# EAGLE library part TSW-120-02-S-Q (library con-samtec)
THROUGH-HOLE .025" SQ POST HEADER Source: Samtec TSW.pdf
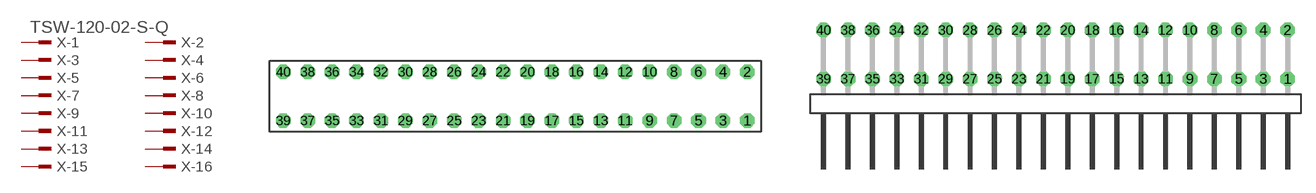
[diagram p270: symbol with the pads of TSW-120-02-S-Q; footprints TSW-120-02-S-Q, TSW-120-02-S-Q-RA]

Designator prefix X; gates -1=MPINV -2=MPIN -3=MPIN -4=MPIN -5=MPIN -6=MPIN -7=MPIN -8=MPIN -9=MPIN -10=MPIN -11=MPIN -12=MPIN -13=MPIN -14=MPIN -15=MPIN -16=MPIN -17=MPIN -18=MPIN -19=MPIN -20=MPIN -21=MPIN -22=MPIN -23=MPIN -24=MPIN -25=MPIN -26=MPIN -27=MPIN -28=MPIN -29=MPIN -30=MPIN -31=MPIN -32=MPIN -33=MPIN -34=MPIN -35=MPIN -36=MPIN -37=MPIN -38=MPIN -39=MPIN -40=MPIN

## TSW-120-02-S-Q (OC_FARNELL: unknown; OC_NEWARK: unknown)  [TSW-120-02-S-Q]
1  -1:1  pas
2  -2:1  pas
3  -3:1  pas
4  -4:1  pas
5  -5:1  pas
6  -6:1  pas
7  -7:1  pas
8  -8:1  pas
9  -9:1  pas
10  -10:1  pas
11  -11:1  pas
12  -12:1  pas
13  -13:1  pas
14  -14:1  pas
15  -15:1  pas
16  -16:1  pas
17  -17:1  pas
18  -18:1  pas
19  -19:1  pas
20  -20:1  pas
21  -21:1  pas
22  -22:1  pas
23  -23:1  pas
24  -24:1  pas
25  -25:1  pas
26  -26:1  pas
27  -27:1  pas
28  -28:1  pas
29  -29:1  pas
30  -30:1  pas
31  -31:1  pas
32  -32:1  pas
33  -33:1  pas
34  -34:1  pas
35  -35:1  pas
36  -36:1  pas
37  -37:1  pas
38  -38:1  pas
39  -39:1  pas
40  -40:1  pas

## TSW-120-02-S-Q-RA (OC_FARNELL: unknown; OC_NEWARK: unknown)  [TSW-120-02-S-Q-RA]
Pads as for TSW-120-02-S-Q

## Footprint TSW-120-02-S-Q (pad centres in mm)
THROUGH-HOLE .025" SQ POST HEADER Source: Samtec TSW.pdf
drill 1 pad 1.5 octagon: 1 24.13,-2.54; 2 24.13,2.54; 3 21.59,-2.54; 4 21.59,2.54; 5 19.05,-2.54; 6 19.05,2.54; 7 16.51,-2.54; 8 16.51,2.54; 9 13.97,-2.54; 10 13.97,2.54; 11 11.43,-2.54; 12 11.43,2.54; 13 8.89,-2.54; 14 8.89,2.54; 15 6.35,-2.54; 16 6.35,2.54; 17 3.81,-2.54; 18 3.81,2.54; 19 1.27,-2.54; 20 1.27,2.54; 21 -1.27,-2.54; 22 -1.27,2.54; 23 -3.81,-2.54; 24 -3.81,2.54; 25 -6.35,-2.54; 26 -6.35,2.54; 27 -8.89,-2.54; 28 -8.89,2.54; 29 -11.43,-2.54; 30 -11.43,2.54; 31 -13.97,-2.54; 32 -13.97,2.54; 33 -16.51,-2.54; 34 -16.51,2.54; 35 -19.05,-2.54; 36 -19.05,2.54; 37 -21.59,-2.54; 38 -21.59,2.54; 39 -24.13,-2.54; 40 -24.13,2.54

## Footprint TSW-120-02-S-Q-RA (pad centres in mm)
THROUGH-HOLE .025" SQ POST HEADER Source: Samtec TSW.pdf
drill 1 pad 1.5 octagon: 1 24.13,1.524; 2 24.13,6.604; 3 21.59,1.524; 4 21.59,6.604; 5 19.05,1.524; 6 19.05,6.604; 7 16.51,1.524; 8 16.51,6.604; 9 13.97,1.524; 10 13.97,6.604; 11 11.43,1.524; 12 11.43,6.604; 13 8.89,1.524; 14 8.89,6.604; 15 6.35,1.524; 16 6.35,6.604; 17 3.81,1.524; 18 3.81,6.604; 19 1.27,1.524; 20 1.27,6.604; 21 -1.27,1.524; 22 -1.27,6.604; 23 -3.81,1.524; 24 -3.81,6.604; 25 -6.35,1.524; 26 -6.35,6.604; 27 -8.89,1.524; 28 -8.89,6.604; 29 -11.43,1.524; 30 -11.43,6.604; 31 -13.97,1.524; 32 -13.97,6.604; 33 -16.51,1.524; 34 -16.51,6.604; 35 -19.05,1.524; 36 -19.05,6.604; 37 -21.59,1.524; 38 -21.59,6.604; 39 -24.13,1.524; 40 -24.13,6.604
